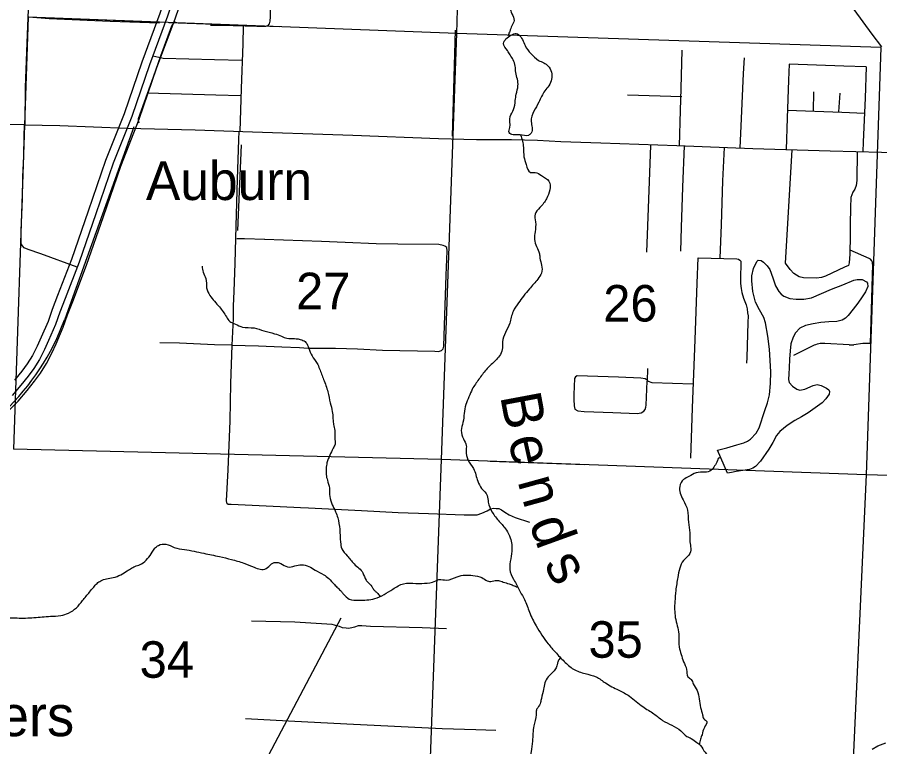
# Model space of a CAD drawing. Extents: x 1219626 to 1426462, y 456797 to 752399.
# Drawn here: x 1327502 to 1338132, y 660041 to 669034 of the extents above; entities that cross this region are included whole.
import ezdxf

# ---------------------------------------------------------------- set-up
doc = ezdxf.new("R2010")
doc.units = 0
for name, color, linetype in [('Communities and Subdivisions Names without Post Office', 7, 'Continuous'), ('County Routes Highway Center Lines', 7, 'Continuous'), ('Lakes and Ponds', 7, 'Continuous'), ('Local Roads Improved', 7, 'Continuous'), ('Local Roads Paved', 7, 'Continuous'), ('Masks', 7, 'Continuous'), ('Narrow River Creek and Branch and Slough', 7, 'Continuous'), ('Narrow River Creek and Branch and Slough Text', 7, 'Continuous'), ('Section Lines', 7, 'Continuous'), ('Section Numbers', 7, 'Continuous'), ('State Route Divided Highway Outline and Fill', 7, 'Continuous'), ('State Routes Highway Center Lines', 7, 'Continuous'), ('Uninventoried Roads and Features', 7, 'Continuous')]:
    doc.layers.add(name, color=color, linetype=linetype)

msp = doc.modelspace()

# ---------------------------------------------------------------- linework, layer by layer
at = {"layer": 'County Routes Highway Center Lines'}
msp.add_lwpolyline([(1338038, 660011), (1338108, 660052), (1338205, 660087)], dxfattribs=at)
at = {"layer": 'Lakes and Ponds'}
msp.add_line((1336256, 663413), (1336130, 663697), dxfattribs=at)
msp.add_lwpolyline([(1336130, 663697), (1336246, 663726), (1336369, 663763), (1336457, 663789), (1336500, 663806), (1336540, 663833), (1336608, 663908), (1336644, 663973), (1336717, 664184), (1336749, 664280), (1336772, 664378), (1336787, 664520), (1336790, 664662), (1336783, 664802), (1336772, 664942), (1336753, 665104), (1336724, 665265), (1336701, 665332), (1336649, 665426), (1336601, 665523), (1336568, 665653), (1336554, 665783), (1336556, 665845), (1336577, 665936), (1336617, 666023), (1336632, 666038), (1336669, 666035), (1336700, 666016), (1336745, 665971), (1336778, 665924), (1336813, 665823), (1336848, 665724), (1336889, 665654), (1336915, 665622), (1336949, 665595), (1337025, 665566), (1337103, 665559), (1337198, 665558), (1337290, 665575), (1337415, 665627), (1337538, 665680), (1337676, 665736), (1337814, 665791), (1337852, 665802), (1337913, 665801), (1337967, 665773), (1337980, 665754), (1337983, 665713), (1337954, 665647), (1337913, 665587), (1337860, 665511), (1337802, 665436), (1337742, 665359), (1337708, 665325), (1337667, 665301), (1337603, 665285), (1337505, 665278), (1337407, 665271), (1337312, 665255), (1337217, 665234), (1337147, 665202), (1337092, 665144), (1337063, 665090), (1337037, 665008), (1337026, 664922), (1337020, 664817), (1337014, 664712), (1337010, 664639), (1337006, 664567), (1337014, 664530), (1337055, 664484), (1337109, 664448), (1337145, 664437), (1337210, 664449), (1337311, 664494), (1337361, 664506), (1337409, 664496), (1337477, 664461), (1337503, 664441), (1337514, 664420), (1337508, 664388), (1337469, 664328), (1337421, 664282), (1337250, 664156), (1337168, 664108), (1337086, 664063), (1336990, 663999), (1336901, 663926), (1336861, 663877), (1336815, 663793), (1336766, 663710), (1336662, 663560), (1336601, 663497), (1336566, 663475), (1336526, 663460), (1336444, 663445), (1336361, 663432), (1336304, 663421), (1336256, 663413)], dxfattribs=at)
for points in [[(1333591, 668813), (1333652, 668834), (1333680, 668820), (1333727, 668759), (1333761, 668684), (1333924, 668501)], [(1333639, 668006), (1333652, 668087), (1333673, 668189), (1333666, 668270), (1333646, 668352), (1333639, 668433), (1333612, 668508), (1333578, 668569), (1333544, 668623), (1333496, 668711), (1333524, 668766), (1333591, 668813)], [(1333924, 668501), (1334046, 668433), (1334086, 668359), (1334086, 668270), (1334053, 668189), (1334005, 668128), (1333930, 667986), (1333869, 667877), (1333836, 667748), (1333836, 667606), (1333802, 667578), (1333700, 667585), (1333612, 667585), (1333564, 667612), (1333571, 667673), (1333578, 667809), (1333619, 667897), (1333639, 668006)]]:
    msp.add_spline(points, degree=3, dxfattribs=at)
at = {"layer": 'Local Roads Improved'}
for p, q in [((1335692, 668053), (1335024, 668075)), ((1337763, 666166), (1337999, 666062)), ((1338044, 665991), (1338014, 665012)), ((1337756, 664994), (1337456, 665012)), ((1337925, 665011), (1337813, 664996)), ((1338014, 665012), (1337973, 665013)), ((1337306, 664982), (1337067, 664865))]:
    msp.add_line(p, q, dxfattribs=at)
for points in [[(1327661, 669847), (1327658, 669666), (1327657, 669514), (1327646, 669279), (1327635, 669130), (1327621, 668719), (1327599, 668169), (1327594, 667708)], [(1329254, 668962), (1328649, 668982), (1327895, 669013), (1327646, 669034)], [(1327594, 667708), (1326986, 667720), (1326464, 667741), (1326321, 667749), (1326287, 667740), (1326264, 667721), (1326247, 667690), (1326241, 667664), (1326232, 667433), (1326219, 666892), (1326216, 666492), (1326213, 666427), (1326210, 666373)], [(1330148, 664990), (1330474, 664983), (1330764, 664970), (1330979, 664962), (1331088, 664953), (1331182, 664956), (1331425, 664953), (1331696, 664945), (1332004, 664931), (1332647, 664917), (1332694, 664915), (1332730, 664925), (1332752, 664948), (1332760, 664979), (1332766, 665233), (1332789, 665853), (1332801, 666151), (1332797, 666194), (1332773, 666212), (1332749, 666222), (1332699, 666231), (1332193, 666236), (1331924, 666242), (1331543, 666258), (1331252, 666268), (1330549, 666293)], [(1334360, 664321), (1334364, 664243), (1334372, 664203), (1334412, 664181), (1334489, 664173), (1334843, 664162), (1335141, 664151), (1335190, 664158), (1335225, 664178), (1335241, 664198), (1335250, 664228), (1335251, 664250)]]:
    msp.add_lwpolyline(points, dxfattribs=at)
for centre, radius, start, end in [((1337969, 665993), 75, 358.2447, 66.1445), ((1337438, 664713), 300, 86.5493, 116.1779), ((1337964, 664713), 300, 88.2447, 97.458), ((1337774, 665294), 300, 266.5493, 277.458)]:
    msp.add_arc(centre, radius, start, end, dxfattribs=at)
at = {"layer": 'Local Roads Paved'}
for p, q in [((1337317, 668115), (1337312, 667876)), ((1337641, 668100), (1337625, 667866)), ((1335270, 664702), (1335264, 664547)), ((1335251, 664250), (1335264, 664547))]:
    msp.add_line(p, q, dxfattribs=at)
for points in [[(1330675, 670813), (1330664, 670579), (1330648, 670043), (1330618, 669258), (1330619, 669116), (1330617, 669040), (1330613, 668984), (1330605, 668952), (1330586, 668928), (1330560, 668919), (1330455, 668922), (1330020, 668933), (1329885, 668934)], [(1337813, 669129), (1338036, 668825), (1338154, 668668)], [(1329450, 668983), (1329416, 668943), (1329404, 668924), (1329269, 668556), (1329176, 668297), (1328992, 667783), (1328993, 667762), (1329002, 667733)], [(1330287, 668926), (1330283, 668706), (1330261, 668154), (1330246, 667627)], [(1335664, 667450), (1335677, 667883), (1335685, 668156), (1335696, 668630)], [(1329173, 668560), (1329284, 668533), (1329302, 668531), (1329934, 668514), (1330275, 668504)], [(1336411, 667422), (1336427, 667787), (1336452, 668340), (1336463, 668533)], [(1337015, 668456), (1337008, 668257), (1336990, 667790), (1336977, 667403)], [(1337965, 668421), (1337689, 668433), (1337015, 668456)], [(1337965, 668422), (1337952, 668035), (1337929, 667500), (1337923, 667376)], [(1330258, 668066), (1329948, 668074), (1329105, 668099)], [(1336994, 667887), (1337664, 667864), (1337944, 667850)], [(1328240, 665953), (1327791, 666116), (1327635, 666169), (1327588, 666193), (1327565, 666215), (1327550, 666240), (1327550, 666255), (1327552, 666407), (1327566, 666795), (1327572, 667066), (1327581, 667319), (1327588, 667569), (1327593, 667708), (1328026, 667698), (1328855, 667665)], [(1328856, 667667), (1329694, 667648), (1330401, 667621), (1331390, 667587), (1331637, 667580), (1332692, 667539), (1333163, 667528), (1333468, 667527), (1333593, 667526), (1333913, 667519), (1334203, 667503), (1334446, 667492), (1334693, 667486), (1335630, 667452), (1336568, 667416), (1337522, 667386), (1338469, 667363), (1339457, 667334), (1339540, 667332)], [(1330231, 667628), (1330227, 667524), (1330213, 667038), (1330196, 666457), (1330182, 666003), (1330171, 665652), (1330164, 665476), (1330161, 665319), (1330148, 664990), (1329934, 664996), (1329501, 665014), (1329261, 665021)], [(1335307, 667454), (1335289, 667008), (1335270, 666463), (1335255, 666136)], [(1335679, 666151), (1335687, 666441), (1335706, 666938), (1335724, 667448)], [(1336214, 667430), (1336195, 667018), (1336179, 666476), (1336162, 666066)], [(1337854, 667378), (1337848, 667023), (1337843, 666959), (1337823, 666915), (1337800, 666876), (1337786, 666846), (1337777, 666810), (1337772, 666689), (1337765, 666480), (1337765, 666349), (1337763, 666113), (1337756, 666006), (1337745, 665974), (1337697, 665951), (1337463, 665843), (1337412, 665825), (1337351, 665818), (1337192, 665823), (1337137, 665834), (1337074, 665873), (1337027, 665924), (1336971, 666001), (1337054, 667401)], [(1330553, 666293), (1330303, 666304), (1330209, 666304)], [(1335805, 663598), (1335824, 664220), (1335856, 665059), (1335882, 665756), (1335894, 666070), (1336372, 666055), (1336392, 666050), (1336408, 666040), (1336419, 666026), (1336420, 666005), (1336415, 665816), (1336415, 665750), (1336425, 665688), (1336433, 665641), (1336454, 665572), (1336485, 665488), (1336499, 665438), (1336502, 665391), (1336510, 665354), (1336507, 665271), (1336492, 664840), (1336490, 664770)], [(1330148, 664990), (1330132, 664519), (1330121, 664060), (1330096, 663454), (1330078, 663073), (1330082, 663053), (1330086, 663043), (1330101, 663031), (1330138, 663031), (1330741, 663003), (1330992, 662991), (1331090, 662985), (1331744, 662954), (1332197, 662930), (1332572, 662917), (1333011, 662900), (1333105, 662898), (1333171, 662900), (1333226, 662922), (1333292, 662948), (1333334, 662972), (1333373, 662980), (1333406, 662979), (1333438, 662976), (1333470, 662962), (1333513, 662932), (1333564, 662899), (1333637, 662865), (1333814, 662809)], [(1335826, 664511), (1335328, 664529), (1335282, 664544), (1335264, 664559), (1335239, 664577), (1335187, 664586), (1334910, 664597), (1334404, 664612), (1334382, 664602), (1334371, 664579), (1334362, 664384), (1334360, 664321)], [(1332792, 661494), (1332494, 661505), (1331855, 661525), (1331747, 661532), (1331703, 661532), (1331658, 661516), (1331624, 661508), (1331584, 661500), (1331556, 661501), (1331512, 661508), (1331473, 661524), (1331438, 661532), (1331412, 661540), (1331382, 661548), (1330923, 661576), (1330388, 661587)], [(1330313, 660388), (1330845, 660360), (1331563, 660324), (1332738, 660267), (1333153, 660255), (1333400, 660243)]]:
    msp.add_lwpolyline(points, dxfattribs=at)
at = {"layer": 'Masks'}
for p, q in [((1329372, 668969), (1330728, 668918)), ((1330262, 667460), (1330216, 666405)), ((1333329, 663562), (1334499, 663519))]:
    msp.add_line(p, q, dxfattribs=at)
msp.add_lwpolyline([(1329209, 668975), (1327638, 669034), (1327539, 666130)], dxfattribs=at)
at = {"layer": 'Narrow River Creek and Branch and Slough'}
for points in [[(1332120, 672902), (1332208, 672841), (1332269, 672807), (1332337, 672719), (1332344, 672603), (1332364, 672488), (1332364, 672400), (1332350, 672284), (1332391, 672183), (1332432, 672088), (1332493, 671952), (1332574, 671823), (1332649, 671728), (1332696, 671626), (1332723, 671470), (1332757, 671348), (1332784, 671280), (1332845, 671192), (1332961, 671090), (1333090, 671009), (1333198, 670941), (1333266, 670880), (1333354, 670744), (1333381, 670629), (1333381, 670473), (1333395, 670330), (1333408, 670215), (1333435, 670106), (1333435, 669998), (1333422, 669815), (1333463, 669679), (1333496, 669570), (1333544, 669442), (1333537, 669333), (1333571, 669151), (1333598, 669077), (1333625, 668995), (1333598, 668927), (1333571, 668860), (1333558, 668819), (1333563, 668793)], [(1333706, 667585), (1333741, 667428), (1333747, 667312), (1333774, 667217), (1333829, 667122), (1333883, 667122), (1333964, 667082), (1334053, 667014), (1334066, 666905), (1334025, 666797), (1333944, 666688), (1333883, 666607), (1333890, 666512), (1333883, 666390), (1333876, 666295), (1333903, 666206), (1333937, 666118), (1333944, 666064), (1333964, 665976), (1333964, 665881), (1333917, 665806), (1333815, 665684), (1333741, 665596), (1333680, 665514), (1333612, 665406), (1333571, 665263), (1333483, 665033), (1333483, 664958), (1333456, 664877), (1333408, 664815), (1333279, 664687), (1333191, 664571), (1333110, 664449), (1333069, 664354), (1333029, 664258), (1332995, 664040), (1332974, 663939), (1333001, 663837), (1333035, 663755), (1333035, 663688), (1333056, 663579), (1333124, 663470), (1333178, 663314), (1333225, 663226), (1333293, 663138), (1333307, 663057), (1333354, 662934), (1333442, 662819), (1333530, 662711), (1333578, 662616), (1333598, 662453), (1333578, 662324), (1333578, 662195), (1333632, 662080), (1333700, 661951), (1333754, 661856), (1333815, 661700), (1333897, 661530), (1334046, 661309), (1334134, 661207), (1334242, 661092), (1334358, 660997), (1334500, 660942), (1334636, 660902), (1334751, 660827), (1334914, 660739), (1335049, 660664), (1335212, 660535), (1335348, 660447), (1335456, 660366), (1335571, 660305), (1335680, 660237), (1335755, 660169), (1335809, 660142), (1335877, 660094), (1335924, 660054), (1335978, 659972), (1336080, 659891), (1336189, 659823), (1336317, 659742), (1336399, 659660), (1336446, 659599), (1336494, 659497), (1336521, 659368), (1336548, 659235), (1336589, 659140), (1336704, 659018), (1336799, 658971), (1336901, 658903), (1336989, 658848), (1337104, 658753)], [(1329780, 665966), (1329795, 665890), (1329826, 665814), (1329836, 665697), (1329876, 665605), (1329993, 665463), (1330080, 665341), (1330120, 665285), (1330191, 665250), (1330278, 665214), (1330420, 665204), (1330542, 665168), (1330674, 665133), (1330760, 665102), (1330826, 665077), (1330918, 665072), (1331009, 665056), (1331060, 665026), (1331095, 664955), (1331136, 664858), (1331197, 664767), (1331227, 664701), (1331278, 664569), (1331329, 664416), (1331359, 664279), (1331385, 664172), (1331400, 664015), (1331415, 663939), (1331415, 663847), (1331420, 663771), (1331395, 663720), (1331354, 663634), (1331319, 663542), (1331309, 663471), (1331309, 663395), (1331324, 663329), (1331349, 663227), (1331354, 663126), (1331385, 663024), (1331425, 662938), (1331451, 662864), (1331476, 662721), (1331486, 662564), (1331502, 662482), (1331568, 662396), (1331654, 662294), (1331761, 662183), (1331801, 662096), (1331832, 662061), (1331882, 662000), (1331908, 661964), (1331938, 661939), (1331971, 661898)], [(1336172, 663603), (1336144, 663598), (1336132, 663568), (1336096, 663502), (1336054, 663449), (1335976, 663425), (1335869, 663419), (1335779, 663371), (1335714, 663335), (1335666, 663251), (1335708, 663084), (1335762, 662959), (1335773, 662809), (1335791, 662678), (1335791, 662565), (1335803, 662487), (1335779, 662403), (1335714, 662338), (1335666, 662242), (1335642, 662129), (1335618, 661967), (1335606, 661830), (1335612, 661633), (1335654, 661430), (1335660, 661269), (1335684, 661179), (1335714, 661089), (1335750, 660994), (1335768, 660904), (1335809, 660868), (1335833, 660816), (1335881, 660732), (1335905, 660630), (1335923, 660523), (1335947, 660433), (1335964, 660386), (1336000, 660350), (1335970, 660278), (1335941, 660188), (1335923, 660135), (1335909, 660067)], [(1326042, 661913), (1326134, 661862), (1326220, 661806), (1326357, 661766), (1326479, 661725), (1326545, 661679), (1326626, 661654), (1326768, 661608), (1326885, 661572), (1326971, 661552), (1327073, 661547), (1327170, 661562), (1327256, 661593), (1327362, 661628), (1327500, 661628), (1327708, 661633), (1327911, 661649), (1328038, 661659), (1328134, 661689), (1328231, 661755), (1328307, 661842), (1328393, 661948), (1328444, 662009), (1328485, 662055), (1328531, 662086), (1328602, 662111), (1328683, 662126), (1328779, 662162), (1328856, 662208), (1328911, 662243), (1328967, 662269), (1329033, 662294), (1329109, 662360), (1329165, 662441), (1329196, 662487), (1329242, 662523), (1329334, 662538), (1329436, 662497), (1329562, 662472), (1329801, 662426), (1329994, 662385), (1330141, 662350), (1330294, 662304), (1330421, 662253), (1330497, 662228), (1330568, 662238), (1330634, 662294), (1330705, 662314), (1330751, 662299), (1330832, 662258), (1330923, 662269), (1331005, 662284), (1331096, 662264), (1331172, 662218), (1331279, 662162), (1331340, 662116), (1331411, 662040), (1331452, 661999), (1331497, 661954), (1331523, 661923), (1331594, 661862), (1331709, 661847), (1331909, 661867), (1332132, 661984), (1332264, 662050), (1332415, 662055), (1332488, 662055), (1332620, 662070), (1332699, 662101), (1332792, 662096), (1332924, 662136), (1333021, 662157), (1333116, 662152), (1333228, 662126), (1333294, 662086), (1333355, 662081), (1333431, 662091), (1333492, 662070), (1333563, 662050), (1333614, 662030), (1333670, 662007)], [(1334199, 661137), (1334167, 661095), (1334157, 661054), (1334137, 661000), (1334096, 660953), (1334045, 660902), (1334005, 660827), (1333988, 660749), (1333961, 660634), (1333951, 660587), (1333917, 660522), (1333900, 660492), (1333896, 660434), (1333869, 660299), (1333852, 660109), (1333836, 659980), (1333822, 659906), (1333798, 659841), (1333761, 659804), (1333724, 659791), (1333511, 659777), (1333365, 659794), (1333294, 659811), (1333213, 659801), (1333165, 659780), (1333125, 659730), (1333097, 659689), (1333091, 659648), (1333070, 659611), (1333020, 659557), (1332949, 659499), (1332850, 659452), (1332776, 659438), (1332667, 659438), (1332579, 659418), (1332491, 659371), (1332417, 659323), (1332292, 659279), (1332200, 659266), (1332136, 659279), (1332058, 659310), (1332001, 659333), (1331963, 659354), (1331923, 659381)]]:
    msp.add_spline(points, degree=3, dxfattribs=at)
at = {"layer": 'Section Lines'}
for p, q in [((1332921, 668835), (1333063, 674089)), ((1327638, 669034), (1327457, 663711)), ((1332921, 668835), (1327638, 669034)), ((1332732, 663583), (1332921, 668835)), ((1338147, 668662), (1332921, 668835)), ((1338147, 668662), (1337966, 663393)), ((1332732, 663583), (1327457, 663711)), ((1332535, 658270), (1332732, 663583)), ((1337966, 663393), (1332732, 663583)), ((1337966, 663393), (1337722, 658106)), ((1343164, 663234), (1337966, 663393))]:
    msp.add_line(p, q, dxfattribs=at)
at = {"layer": 'State Route Divided Highway Outline and Fill'}
for points in [[(1329675, 670356), (1329637, 670228), (1329549, 669925), (1329474, 669707), (1329451, 669647), (1329261, 669081), (1329036, 668480), (1328818, 667845), (1328591, 667269), (1328374, 666643), (1328169, 666047), (1327998, 665603), (1327932, 665433), (1327881, 665284), (1327797, 665088), (1327749, 664980), (1327689, 664864), (1327623, 664760), (1327557, 664671), (1327469, 664560)], [(1327394, 664182), (1327512, 664301), (1327623, 664433), (1327716, 664549), (1327787, 664647), (1327863, 664764), (1327929, 664894), (1327980, 665008), (1328068, 665212), (1328120, 665365), (1328185, 665531), (1328357, 665979), (1328563, 666577), (1328779, 667199), (1329006, 667776), (1329224, 668413), (1329450, 669014), (1329640, 669580), (1329662, 669639), (1329740, 669865), (1329829, 670172), (1329866, 670300)]]:
    msp.add_lwpolyline(points, dxfattribs=at)
at = {"layer": 'State Routes Highway Center Lines'}
msp.add_lwpolyline([(1329770, 670328), (1329733, 670200), (1329645, 669895), (1329568, 669673), (1329546, 669614), (1329355, 669047), (1329130, 668447), (1328912, 667810), (1328685, 667234), (1328469, 666610), (1328263, 666013), (1328091, 665567), (1328026, 665399), (1327975, 665248), (1327888, 665048), (1327839, 664937), (1327776, 664814), (1327705, 664703), (1327636, 664610), (1327546, 664497), (1327438, 664369)], dxfattribs=at)
at = {"layer": 'Uninventoried Roads and Features'}
for p, q in [((1332897, 668876), (1332862, 667569)), ((1328940, 667685), (1328087, 665313)), ((1330491, 659731), (1331493, 661630))]:
    msp.add_line(p, q, dxfattribs=at)
msp.add_arc((1325328, 666306), 2932, 286.6522, 340.2212, dxfattribs=at)

# ---------------------------------------------------------------- texts
at = {"layer": 'Communities and Subdivisions Names without Post Office'}
msp.add_text('Auburn', height=475, rotation=359.9998, dxfattribs=at).set_placement((1329088, 666781))
at = {"layer": 'Narrow River Creek and Branch and Slough Text'}
for s, rotation, p in [('B', 280.6364, (1333452, 664364)), ('e', 282.5528, (1333550, 663838)), ('n', 285.404, (1333666, 663315)), ('d', 289.8936, (1333806, 662798)), ('s', 299.0706, (1333984, 662291)), ('Flowers', 359.9998, (1325863, 660171))]:
    msp.add_text(s, height=500, rotation=rotation, dxfattribs=at).set_placement(p)
at = {"layer": 'Section Numbers'}
for s, p in [('27', (1330938, 665435)), ('26', (1334724, 665283)), ('35', (1334542, 661138)), ('34', (1329010, 660891))]:
    msp.add_text(s, height=450, rotation=359.9998, dxfattribs=at).set_placement(p)

doc.saveas('drawing.dxf')
